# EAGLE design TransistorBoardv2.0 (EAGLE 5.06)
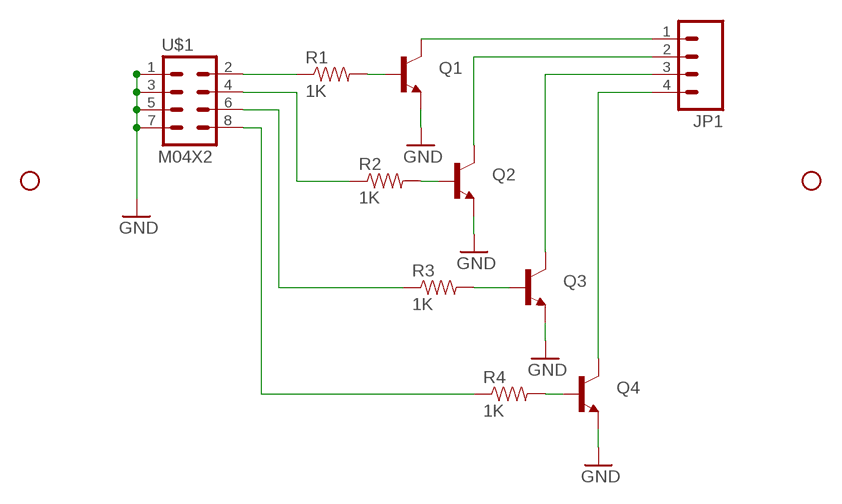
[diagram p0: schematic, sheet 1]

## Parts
JP1  M04PTH  [1X04]
JP2  STAND-OFF  [STAND-OFF]
JP3  STAND-OFF  [STAND-OFF]
Q1  TRANSISTOR_NPNSOT23  [SOT23]
Q2  TRANSISTOR_NPNSOT23  [SOT23]
Q3  TRANSISTOR_NPNSOT23  [SOT23]
Q4  TRANSISTOR_NPNSOT23  [SOT23]
R1  1K  RESISTOR1206  [1206]
R2  1K  RESISTOR1206  [1206]
R3  1K  RESISTOR1206  [1206]
R4  1K  RESISTOR1206  [1206]
U$1  M04X2  [2X4]

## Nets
GND: Q1.2(E) Q2.2(E) Q3.2(E) Q4.2(E) U$1.1 U$1.3 U$1.5 U$1.7
N$1: Q1.1(B) R1.2
N$2: Q2.1(B) R2.2
N$3: Q3.1(B) R3.2
N$4: Q4.1(B) R4.2
N$5: R1.1 U$1.2
N$6: JP1.1 Q1.3(C)
N$7: JP1.2 Q2.3(C)
N$8: JP1.3 Q3.3(C)
N$9: JP1.4 Q4.3(C)
N$10: R2.1 U$1.4
N$11: R3.1 U$1.6
N$12: R4.1 U$1.8

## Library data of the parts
JP1 = SparkFun:M04: Header 4 Standard 4-pin 0.1" header. Use with straight break away headers (SKU : PRT-00116), right angle break away headers (PRT-00553), swiss pins (PRT-00743), machine pins (PRT-00117), and female headers (PRT-00115). Molex polarized connector foot print use with SKU : PRT-08231 with associated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
JP2 JP3 = SparkFun:STAND-OFF: Stand Off
Q1-Q4 = SparkFun:TRANSISTOR_NPN: Transistor NPN BJT configuration in SOT23 package. MMBT2222 is the common NPN we use. Double check BCE configuration again layout.
R1-R4 = SparkFun:RESISTOR: Resistor
U$1 = SparkFun:M04X2

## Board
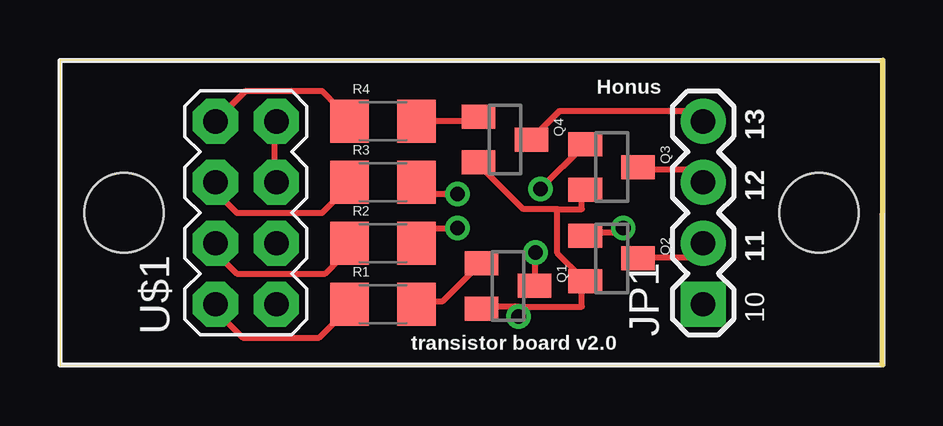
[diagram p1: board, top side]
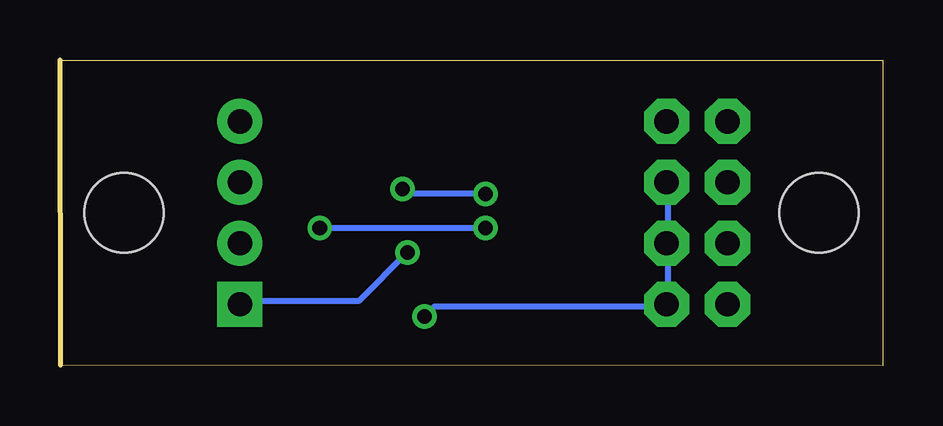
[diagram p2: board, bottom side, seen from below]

Size 34.29 x 12.74 mm. Coordinates in mm from the lower left corner, seen from the top.
Outline: 0,0 34.27,0.03 34.29,12.74 0,12.74 0,0
Copper layers (1*16): Top 0.035mm / dielectric 1.5mm / Bottom 0.035mm
Design rules "default": minimum track width 10mil, minimum drill 24mil, track to track 8mil, track to pad 8mil, pad to pad 8mil, via to via 8mil, smd to smd 8mil, copper to edge 40mil, drill to drill 8mil, minimum pad ring 10mil, minimum via ring 8mil, stop-mask expansion 4mil, vias tented up to drill 0mil, thermal gap 10mil

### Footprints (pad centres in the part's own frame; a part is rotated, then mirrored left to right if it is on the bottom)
1X04 = drill 1.016 pad 1.88 square: 1 0,0 | drill 1.016 pad 1.88 round: 2 2.54,0; 3 5.08,0; 4 7.62,0
STAND-OFF = hole 3.302: 0,0
SOT23 = smd 1 x 1.4: 1 -0.95,-1.1; 2 0.95,-1.1; 3 0,1.1
1206 = smd 1.6 x 1.8: 1 -1.4,0; 2 1.4,0
2X4 = drill 1.016 pad 1.88 octagon: 1 -3.81,-1.27; 2 -3.81,1.27; 3 -1.27,-1.27; 4 -1.27,1.27; 5 1.27,-1.27; 6 1.27,1.27; 7 3.81,-1.27; 8 3.81,1.27

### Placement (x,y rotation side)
JP1  26.8,2.57 90 top
JP2  2.67,6.38 0 top
JP3  31.62,6.38 0 top
Q1  18.67,3.33 270 top
Q2  22.99,4.47 270 top
Q3  22.99,8.28 270 top
Q4  18.54,9.42 270 top
R1  13.46,2.57 0 top
R2  13.46,5.11 0 top
R3  13.46,7.65 0 top
R4  13.46,10.19 0 top
U$1  7.75,6.38 90 top

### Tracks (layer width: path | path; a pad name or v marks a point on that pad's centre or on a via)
GND  (via drill 0.61)
  Top 0.254: 19.1,2.46 21.74,2.46 21.74,3.48 Q2.2 21.74,3.68 20.73,4.7 20.73,6.53 | 19.1,2.46 17.68,2.46 Q1.2 | 20.73,6.53 21.74,6.53 21.74,7.14 Q3.2 | 20.73,6.53 19.3,6.53 17.48,8.36 Q4.2 | U$1.5 8.94,7.75 8.94,10.19 U$1.7 | v19.1,2.06 19.1,2.46
  Bottom 0.254: 8.94,5.11 8.94,2.67 U$1.1 9.14,2.46 18.69,2.46 v19.1,2.06 | 8.94,5.11 8.94,7.54 U$1.5 | 8.94,5.11 U$1.3
N$1
  Top 0.254: Q1.1 17.37,4.11 15.95,2.69 14.94,2.69 R1.2
N$2  (via drill 0.61)
  Top 0.254: v23.47,5.74 23.47,5.54 22.05,5.54 Q2.1 | v16.56,5.74 14.94,5.74 14.94,5.13 R2.2
  Bottom 0.254: v16.56,5.74 v23.47,5.74
N$3  (via drill 0.61)
  Top 0.254: v20.02,7.37 21.84,9.19 Q3.1 | v16.56,7.16 14.94,7.16 14.94,7.57 R3.2
  Bottom 0.254: v20.02,7.37 19.81,7.16 v16.56,7.16
N$4
  Top 0.254: Q4.1 17.37,10.21 14.94,10.21 R4.2
N$5
  Top 0.254: U$1.2 6.48,2.31 7.62,1.17 10.79,1.17 12.19,2.57 12.19,3.2 12.06,3.07 R1.1
N$6  (via drill 0.61)
  Top 0.254: v19.81,4.72 19.81,3.51 Q1.3
  Bottom 0.254: v19.81,4.72 21.84,2.69 26.72,2.69 JP1.1
N$7
  Top 0.254: Q2.3 24.28,4.52 26.72,4.52 26.72,4.93 JP1.2
N$8
  Top 0.254: Q3.3 24.28,8.18 26.72,8.18 26.72,7.77 JP1.3
N$9
  Top 0.254: Q4.3 19.81,9.6 20.83,10.62 26.72,10.62 26.72,10.21 JP1.4
N$10
  Top 0.254: U$1.4 6.48,4.72 7.37,3.84 11.05,3.84 11.68,4.47 11.68,4.73 R2.1
N$11
  Top 0.254: U$1.6 6.48,7.26 7.37,6.38 10.92,6.38 11.43,6.88 11.43,7.01 R3.1
N$12
  Top 0.254: U$1.8 7.75,11.46 10.92,11.46 11.56,10.82 11.56,10.69 R4.1

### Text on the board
tPlace: Honus | 13 | 12 | 11 | 10 | transistor board v2.0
